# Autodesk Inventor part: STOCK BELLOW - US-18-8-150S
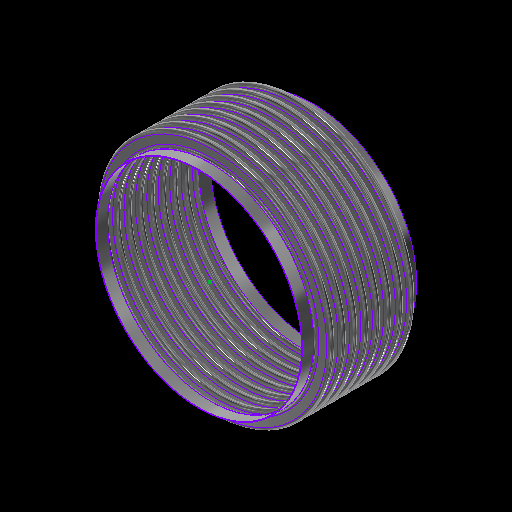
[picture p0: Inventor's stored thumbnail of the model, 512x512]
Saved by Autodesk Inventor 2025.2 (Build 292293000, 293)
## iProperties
Category: 16 GA (0.060 THICK)
RuleStatus: InUse
Created: 2024-01
Part Number: STOCK BELLOW - US-18-8-150S
Project: =STOCK BELLOWS: <Stock Number><SFILL>
Material: ASTM A240-304
Description: =STOCK BELLOWS: <Stock Number>, <SID_> I.D., <SOD_> O.D., <SPLY_> PLY, <Category>, <SNET_CONS> CONS.<PITCH_><STANGENT_> TANGENT<SFILL>
Document SubType Name: Sheet Metal
Designer: GS
Stock Number: U.S-18-8-150S
Surface Area: 20016.7 cm^2
Volume: 1515.23 cm^3
Sheet Metal Rule: Default
Appearance: STAINLESS STEEL
Mass: 12208.7 g
Density: 8.05729 g/cm^3
THK: 0.036
ID: 3.500
OD: 4.250
CONS_: 2
PITCH: 0.500
TANGENT: 0.500
BELLOWS_UPSET: 0.000
d79: 1.000
d82: 1.000
d83: 26.000
d84: 24.000
d174: 8
d214: 8
STHK_: 0.060
SID_: 18.000
SOD_: 20.500
SPITCH_: 1.000
STANGENT__: 1.000
SBELLOWS_UPSET_: 0.000
SDIFF_TAN: 1.000
d252: 2
d275: 2
d287: 0.050
d289: 0.500
d290: 0.000
SOD_NECK: 18 1/8
PLY: 1
PSET: 4.178
PBAR: 1.035
COUNTER: 1.500
NET_TUBE: 3.071
CONS: 2
S_CONS: 0
NET_CONS: 2
ID_M: 88.90 mm
OD_M: 107.95 mm
THK_M: 0.91 mm
ID_U: 3.500 in
OD_U: 4.250 in
THK_U: 0.036 in
TANGENT2: 0.500
TAN_TO_TAN: 1.000 in
d80: 2.571
d81: 10
SID: 2.375
SCONS_: 8
SPITCH: 0.250
STANGENT_: 1.000
SBELLOWS_UPSET: 0.000
SNET_CONS: 8
SS_CONS: 0
SCONS: 8
d190: 8
d191: 1
d192: 1
d193: 8
d194: 0
SIZE: 18.00
PRESSURE: 150
d230: 8
STANGENT: 4.000
SPLY_: 1
d233: 8
d234: 0
d263: 2
d265: 1
d268: 2
d269: 0
d286: 2
d288: 1
d291: 2
d292: 0
SREROLL: 0.750
BLETP: 0.000 ul
PRES_Copy: 85
MATTABLE: 20 GA (0.036 THICK)
PART_NUMBER: U.S-18-8-150S
PITCH_: =, <SPITCH_> PITCH,
CFILL: .
SFILL: .
MESH: ,
COMP: 1.5
EXT: 0.75
LAT: 0.20
ANG: 516
ASR: 5052
LSR: 39491
ANSR: 3676
PRES: 150
COMPM: 15.0
EXTM: 7.5
LATM: 2.00
ASRM: 884.757
PRESM: 10.342
LSRM: 6916.059
ANSRM: 643.778
TEMPMIN: 20
TEMPMAX: 800
TEMPMINM: -7
TEMPMAXM: 427
WEIGHTM: 12.209
WEIGHT: 26.915
Author: GS
Keywords: 20 GA (0.036 THICK)
Comments: =STOCK BELLOW - <STOCK NUMBER>
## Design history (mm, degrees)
sketch "Sketch2"
  geometry: L1 (0, -177.245)-(0, 562.856) reference; L2 (45.364, 0)-(44.45, 0); L3 (48.082, -2.718)-(50.343, -2.718); L4 (48.082, -3.632)-(50.343, -3.632); L5 (50.343, -9.982)-(48.082, -9.982); L6 (50.343, -9.068)-(48.082, -9.068); L7 (45.364, -12.7)-(44.45, -12.7); L8 (48.082, 0)-(48.082, -12.7); L9 (50.343, -6.35)-(53.975, -6.35); L10 (44.45, 0)-(44.45, -12.7); L11 (20.376, 102.841)-(20.376, 101.926); L12 (58.262, 457.127)-(58.262, 349.177); L13 (58.262, 444.427)-(58.262, 336.477); L14 (93.133, -58.817)-(93.133, -71.517); L15 (118.746, -66.401)-(118.746, -66.401); L16 (50.343, -9.068)-(50.343, -9.982); L17 (48.082, -9.068)-(48.082, -9.982); L18 (48.082, -9.525)-(50.343, -9.525); L19 (53.975, 0)-(53.975, -12.7); L20 (-50.343, -9.068)-(-50.343, -9.982); L21 (-50.343, -2.718)-(-48.082, -2.718); L22 (-50.343, -3.632)-(-48.082, -3.632); L23 (-48.082, -9.068)-(-50.343, -9.068); L24 (-50.343, -9.525)-(-48.082, -9.525); L25 (-48.082, -9.982)-(-50.343, -9.982); L26 (-48.082, -9.068)-(-48.082, -9.982); L27 (-44.45, 0.653)-(-44.45, -12.047); L28 (-48.082, -6.35)-(-44.45, -6.35); L29 (-50.343, 0.653)-(-50.343, -12.7); L30 (-53.061, 0)-(-53.975, 0); L31 (-53.975, 0)-(-53.975, -12.7); L32 (-53.061, -12.7)-(-53.975, -12.7); A1 r 2.718 centre (48.082, 0) between (45.364, 0) and (48.082, -2.718); A2 r 3.632 centre (48.082, 0) between (44.45, 0) and (48.082, -3.632); A3 r 3.632 centre (50.343, -6.35) between (50.343, -9.982) and (50.343, -2.718); A4 r 2.718 centre (50.343, -6.35) between (50.343, -9.068) and (50.343, -3.632); A5 r 2.718 centre (48.082, -12.7) between (48.082, -9.982) and (45.364, -12.7); A6 r 3.632 centre (48.082, -12.7) between (48.082, -9.068) and (44.45, -12.7); A7 r 3.175 centre (50.343, -6.35) between (50.343, -9.525) and (53.518, -6.35); A8 r 3.175 centre (48.082, -12.7) between (48.082, -9.525) and (44.907, -12.7); A9 r 2.718 centre (-50.343, -12.7) between (-50.343, -9.982) and (-53.061, -12.7); A10 r 2.718 centre (-48.082, -6.35) between (-48.082, -9.068) and (-48.082, -3.632); A11 r 3.175 centre (-48.082, -6.35) between (-48.082, -9.525) and (-44.907, -6.35); A12 r 3.632 centre (-48.082, -6.35) between (-48.082, -9.982) and (-48.082, -2.718); A13 r 3.175 centre (-50.343, -12.7) between (-50.343, -9.525) and (-53.518, -12.7); A14 r 3.632 centre (-50.343, -12.7) between (-50.343, -9.068) and (-53.975, -12.7); A15 r 2.718 centre (-50.343, 0) between (-53.061, 0) and (-50.343, -2.718); A16 r 3.632 centre (-50.343, 0) between (-53.975, 0) and (-50.343, -3.632); 10 further points
  constraints: 62 end point, 38 point on circle, 20 tangent, 16 centre point, 12 parallel, 9 midpoint, 7 vertical, 6 coincident, 6 concentric, 6 point on line, 4 equal radius, 4 perpendicular, 3 horizontal, 1 collinear, 1 horizontal alignment, 10 other
  dimensions: "THK" = 0.9144 distance of L11.start L11.end; "ID" = 88.9 distance of L11.end point (20.376, 13.026); "OD" = 107.95 distance of L12.start L12.end; "PITCH" = 12.7 distance of L12.start L13.start; "TANGENT" = 12.7 distance of L14.start L14.end; "BELLOWS_UPSET" = 0 distance of L15.start L15.end; "d43" = 88.9 diameter of L10 L1 (= ID); "d44" = 107.95 diameter of L9.end L1 (= OD); "d45" = 0.9144 distance between parallel lines of L5 L6 (computed from THK, PLY); "d46" = 3.6322 radius of A3 (computed from PITCH, THK, PLY); "UPSET_PITCH" = 12.7 distance of L2.end L7.end (derived); "SIDEWALL_ANGLE" = 360 deg dimension on L3 L9 (derived); "CON_GAP" = 5.4356 distance of point (48.082, -9.068) point (48.082, -3.632) (derived); "TAN1" = 4.98728 dimension on A8 (derived); "TAN2" = 4.98728 dimension on A7 (derived); "LEG1" = 2.2606 distance of L18.start L18.end (derived); "d278" = 0.9144 distance between parallel lines of L25 L23 (derived); "d279" = 3.6322 radius of A12 (derived); "d280" = 12.7 distance of L30.end L31.end (derived); "d281" = 360 deg dimension on L21 L28 (derived); "d282" = 5.4356 distance of point (-50.343, -9.068) point (-50.343, -3.632) (derived); "d283" = 4.98728 dimension on A13 (derived); "d284" = 4.98728 dimension on A11 (derived); "d285" = 2.2606 distance of L24.start L24.end (derived); "d293" = 88.9 diameter of L27 L1 (derived); "d294" = 107.95 diameter of L31 L1 (derived)
  node "Sketch Rectangular Pattern1" dims "d31" = 25.4, "ID" = 88.9
  node "Sketch Rectangular Pattern2" dims "d39" = 25.4, "PITCH" = 12.7
revolve "CONS" stored, may be unused: angle "d48" = 90 deg
node "BELLOW MIDPLANE"
pattern_linear "Rectangular Pattern2" dims "d52" = 12.7 (= UPSET_PITCH)
sketch "Sketch5"
  geometry: C1 r 45.364 at (0, 0) reference; C2 r 44.45 at (0, 0) reference
extrude "TANGENT" new body sketch "Sketch5" distance "d53" = 12.7 (= TANGENT); taper "d54" = 0 deg
revolve "SAMETAN" stored, may be unused: angle "d65" = 90 deg
revolve "DIFFTAN" stored, may be unused: angle "d70" = 90 deg
sketch "Sketch9"
  geometry: L1 (53.319, 0)-(-53.319, 0) reference; L2 (0, -17.78)-(0, 17.78) reference; L3 (38.085, 0)-(-38.085, 0); L4 (38.085, -11.906)-(38.085, 11.906); L5 (25.385, -11.906)-(25.385, 11.906); L6 (13.15, 11.906)-(13.15, -11.906); L7 (-25.385, -11.906)-(-25.385, 11.906); L8 (-38.085, -11.906)-(-38.085, 11.906); L9 (37.291, -11.906)-(37.291, 11.906); L10 (38.085, -11.906)-(37.291, -11.906); L11 (38.085, 11.906)-(37.291, 11.906); L12 (13.546, 11.906)-(12.753, 11.906); L13 (12.753, 11.906)-(12.753, -11.906); L14 (12.753, -11.906)-(13.546, -11.906); L15 (13.546, -11.906)-(13.546, 11.906); L16 (-13.546, 11.906)-(-13.546, -11.906); L17 (-13.15, 11.906)-(-13.15, -11.906); L18 (-13.546, -11.906)-(-12.753, -11.906); L19 (-12.753, -11.906)-(-12.753, 11.906); L20 (-12.753, 11.906)-(-13.546, 11.906); L21 (-38.085, -11.906)-(-37.291, -11.906); L22 (-37.291, -11.906)-(-37.291, 11.906); L23 (-37.291, 11.906)-(-38.085, 11.906); L24 (-38.085, 11.906)-(-38.085, -11.906); L25 (38.085, -0.397)-(-38.085, -0.397); L26 (-38.085, -0.397)-(-38.085, 0.397); L27 (-38.085, 0.397)-(38.085, 0.397); L28 (38.085, 0.397)-(38.085, -0.397); L29 (-38.085, 11.906)-(38.085, 11.906); L30 (38.085, 11.906)-(38.085, 12.7); L31 (38.085, 12.7)-(-38.085, 12.7); L32 (-38.085, 12.7)-(-38.085, 11.906); L33 (38.085, -11.906)-(-38.085, -11.906); L34 (-38.085, -11.906)-(-38.085, -12.7); L35 (-38.085, -12.7)-(38.085, -12.7); L36 (38.085, -12.7)-(38.085, -11.906); 30 further points
  constraints: 68 end point, 13 midpoint, 13 parallel, 8 horizontal, 7 perpendicular, 6 equal length, 3 point on line, 2 vertical, 14 other
  dimensions: "d115" = 23.8125 distance of L4.start L4.end (derived); "d116" = 12.7 distance between parallel lines of L4 L5 (derived); "d117" = 12.23516 distance between parallel lines of L5 L6 (derived); "d125" = 38.53427 distance between parallel lines of L7 L6 (derived); "d127" = 12.7 distance between parallel lines of L8 L7 (derived); "d128" = 24.93516 distance between parallel lines of L6 L4 (derived); "d130" = 76.16943 distance between parallel lines of L8 L4 (derived); "RULER_THK" = 0.79375 distance between parallel lines of L4 L9; "d135" = 0.79375 distance of L13.end L14.end (derived); "d138" = 26.29911 distance of L13.end L16.end (derived); "d143" = 0.79375 distance of L22.end L8.end (derived); "d144" = 0.79375 distance between parallel lines of L27 L25 (derived)
extrude "RULER" join sketch "Sketch9" distance "d149" = 0.79375 (derived); taper "d150" = 0 deg
extrude "BARS" join sketch "Sketch9" distance "d151" = 0.79375 (derived); taper "d152" = 0 deg
pattern_linear "Rectangular Pattern4" dims "d155" = 26.29911 (derived)
sketch "Sketch13"
  geometry: L1 (93.149, -52.467)-(93.149, -77.867); L2 (230.124, 0)-(228.6, 0); L3 (230.124, -25.4)-(228.6, -25.4); L4 (253.238, -19.812)-(235.712, -19.812); L5 (253.238, -18.288)-(235.712, -18.288); L6 (253.238, -12.7)-(260.35, -12.7); L7 (235.712, -5.588)-(253.238, -5.588); L8 (235.712, 0)-(235.712, -25.4); L9 (228.6, 0)-(228.6, -25.4); L10 (58.254, 24.269)-(58.254, -496.431); L11 (58.254, -1.131)-(58.254, -521.831); L12 (58.254, -51.931)-(58.254, -572.631); L13 (58.254, -77.331)-(58.254, -598.031); L14 (58.254, -102.731)-(58.254, -623.431); L15 (58.254, -128.131)-(58.254, -648.831); L16 (58.254, -153.531)-(58.254, -674.231); L17 (58.254, -26.531)-(58.254, -547.231); L18 (20.376, 103.45)-(20.376, 101.926); L19 (235.712, -7.112)-(253.238, -7.112); L20 (0, -829.767)-(0, 258.986) reference; L21 (-52.07, 0)-(312.42, 0) reference; A1 r 5.588 centre (235.712, 0) between (230.124, 0) and (235.712, -5.588); A2 r 5.588 centre (235.712, -25.4) between (235.712, -19.812) and (230.124, -25.4); A3 r 7.112 centre (235.712, -25.4) between (235.712, -18.288) and (228.6, -25.4); A4 r 5.588 centre (253.238, -12.7) between (253.238, -18.288) and (253.238, -7.112); A5 r 7.112 centre (253.238, -12.7) between (253.238, -19.812) and (253.238, -5.588); A6 r 7.112 centre (235.712, 0) between (228.6, 0) and (235.712, -7.112); 6 further points; 1 other entity
  constraints: 38 end point, 15 point on circle, 9 tangent, 6 centre point, 6 parallel, 5 vertical alignment, 4 point on line, 4 vertical, 3 coincident, 3 concentric, 2 collinear, 2 equal radius, 1 horizontal, 1 perpendicular, 23 other
  dimensions: "SBELLOWS_UPSET_" = 0 distance of point (118.762, -66.401) point (118.762, -66.401); "STOTAL_THK_BELLOW__" = 1.524 distance between parallel lines of L4 L5 (derived); "d224" = 7.112 radius of A5 (derived); "d225" = 25.4 distance of L2.end L3.end (derived); "SSIDEWALL_ANGLE_" = 360 deg dimension on L7 L6 (derived); "SSCON_GAP_" = 11.176 distance of point (235.712, -18.288) point (235.712, -7.112) (derived); "d235" = 457.2 diameter of L9 L20 (derived); "d236" = 520.7 diameter of L6.end L20 (derived)
  node "Sketch Rectangular Pattern4" dims "d228" = 25.4
  node "Sketch Rectangular Pattern5" dims "d229" = 25.4
revolve "SBELLOW" stored, may be unused: angle "d197" = 90 deg
pattern_linear "Rectangular Pattern5" dims "d204" = 25.4 (derived)
revolve "STANGENT" stored, may be unused: angle "d240" = 90 deg
revolve "SSAMETAN" stored, may be unused: angle "d241" = 90 deg
revolve "SDIFFTAN" stored, may be unused: angle "d246" = 90 deg
revolve "INVCON" stored, may be unused: angle "d295" = 90 deg
pattern_linear "Rectangular Pattern6" dims "d298" = 12.7 (derived)
revolve "INVTANGENT" stored, may be unused: angle "d302" = 90 deg
revolve "INVSAMETAN" stored, may be unused: angle "d307" = 90 deg
revolve "INVDIFFTAN" stored, may be unused: angle "d312" = 90 deg
sketch "ID BELLOW MOUNT CALC"
  geometry: L1 (44.45, 0)-(38.1, 0); L2 (38.1, 0)-(38.1, 12.7); L3 (38.1, 12.7)-(44.45, 12.7); L4 (44.45, 12.7)-(44.45, 0); L5 (36.513, 12.7)-(35.598, 12.7); L6 (35.598, 12.7)-(35.598, 0); L7 (35.598, 0)-(36.513, 0); L8 (36.513, 0)-(36.513, 12.7); L9 (0, -2.54)-(0, 15.24) reference; L10 (-8.89, 0)-(53.34, 0) reference; 1 further point
  constraints: 16 end point, 5 parallel, 2 collinear, 2 horizontal, 2 perpendicular
  dimensions: "d314" = 12.7 distance of L5.end L6.end (derived); "d315" = 0.9144 distance of L5.start L5.end (derived); "IG" = 1.5875 distance between parallel lines of L2 L8; "PIPE_OD" = 88.9 diameter of L4 L9; "PIPE_WALL" = 6.35 distance of L2.end L3.end; "ID_MT_BELLOW" = 71.1962 diameter of L6 L9 (derived)
revolve "CFILL" stored, may be unused: angle "d320" = 90 deg
pattern_linear "Rectangular Pattern7" dims "d323" = 12.7 (derived)
revolve "SFILL" stored, may be unused: angle "d324" = 90 deg
pattern_linear "Rectangular Pattern8" dims "d327" = 25.4 (derived)
node "STOCK BELLOW MIDPLANE"
node "BELLOW"
sketch "Sketch6"
  geometry: L1 (-12.7, 45.364)-(0, 45.364); L2 (0, 45.364)-(0, 44.45); L3 (0, 44.45)-(-12.7, 44.45); L4 (-12.7, 44.45)-(-12.7, 45.364); L5 (10.16, 0)-(-60.96, 0) reference; L6 (-38.1, -89.422)-(-38.1, 153.44) reference; 1 further point
  constraints: 8 end point, 2 parallel, 1 horizontal, 1 perpendicular
  dimensions: "d61" = 12.7 distance of L2.end L3.end (derived); "d62" = 0.9144 distance of L1.end L2.end (derived); "d63" = 88.9 diameter of L3 L5 (derived); "d64" = 25.4 distance between parallel lines of L4 L6 (derived)
sketch "Sketch12"
  geometry: 1 further point
sketch "Sketch14"
  geometry: L1 (-25.4, 230.124)-(0, 230.124); L2 (0, 230.124)-(0, 228.6); L3 (0, 228.6)-(-25.4, 228.6); L4 (-25.4, 228.6)-(-25.4, 230.124); L5 (5.08, 0)-(-30.48, 0) reference; L6 (0, -46.025)-(0, 276.149) reference; 1 further point
  constraints: 8 end point, 2 parallel, 1 collinear, 1 horizontal, 1 perpendicular
  dimensions: "d237" = 1.524 distance of L3.end L1.start (derived); "d238" = 457.2 diameter of L3 L5 (derived); "d239" = 25.4 distance of L1.start L1.end (derived); "SOD_NECK" = 460.248 diameter of L1 L5 (derived)
sketch "Sketch15"
  geometry: L1 (-46.025, 0)-(276.149, 0) reference; L2 (228.6, -203.2)-(230.124, -203.2); L3 (230.124, -203.2)-(230.124, -228.6); L4 (230.124, -228.6)-(228.6, -228.6); L5 (228.6, -228.6)-(228.6, -203.2); L6 (0, -276.86)-(0, 60.96) reference; 1 further point
  constraints: 8 end point, 2 parallel, 1 horizontal, 1 perpendicular
  dimensions: "d205" = 25.4 distance of L4.end L2.start (derived); "d206" = 1.524 distance of L3.end L4.end (derived); "d207" = 457.2 diameter of L5 L6 (derived); "d208" = 203.2 distance between parallel lines of L1 L2 (derived)
node "TANGENT_"
node "SAME_TAN"
sketch "Sketch8"
  geometry: L1 (45.364, -25.4)-(44.45, -25.4); L2 (44.45, -25.4)-(44.45, -38.1); L3 (44.45, -38.1)-(45.364, -38.1); L4 (45.364, -38.1)-(45.364, -25.4); L5 (0, -48.26)-(0, 22.86) reference; L6 (-89.422, 0)-(153.44, 0) reference; 1 further point
  constraints: 8 end point, 2 parallel, 1 horizontal, 1 perpendicular
  dimensions: "d66" = 88.9 diameter of L2 L5 (derived); "TOTAL_THK_BELLOW" = 0.9144 distance of L2.end L3.end (derived); "d68" = 25.4 distance between parallel lines of L1 L6 (derived); "d69" = 12.7 distance of L1.end L2.end (derived)
node "DIFF_TAN"
node "Sketch Rectangular Pattern3" dims "d138" = 26.29911 (derived), "d141" = 25.4
node "SBELLOW_"
node "STANGENT_"
node "SSAME_TAN"
sketch "Sketch16"
  geometry: L1 (230.124, -203.2)-(228.6, -203.2); L2 (228.6, -203.2)-(228.6, -228.6); L3 (228.6, -228.6)-(230.124, -228.6); L4 (230.124, -228.6)-(230.124, -203.2); L5 (0, -276.86)-(0, 60.96) reference; L6 (-46.025, 0)-(276.149, 0) reference; 1 further point
  constraints: 8 end point, 2 parallel, 1 horizontal, 1 perpendicular
  dimensions: "SDIFF_TAN" = 25.4 distance of L3.end L1.start; "d243" = 1.524 distance of L2.end L3.end (derived); "d244" = 203.2 distance between parallel lines of L1 L6 (derived); "d245" = 457.2 diameter of L2 L5 (derived)
node "SDIFF_TAN"
body "Solid15"
sketch "Sketch17"
  geometry: L1 (53.975, 12.7)-(53.061, 12.7); L2 (53.061, 12.7)-(53.061, 0); L3 (53.061, 0)-(53.975, 0); L4 (53.975, 0)-(53.975, 12.7); L5 (0, -2.54)-(0, 15.24) reference; L6 (-10.795, 0)-(64.77, 0) reference; 2 further points
  constraints: 8 end point, 2 parallel, 1 horizontal, 1 midpoint, 1 perpendicular, 1 point on line
  dimensions: "INVTANGENT" = 12.7 distance of L3.end L1.start (derived); "d300" = 0.9144 distance of L1.start L1.end (derived); "d301" = 107.95 diameter of L4 L5 (derived)
body "Solid16"
sketch "Sketch18"
  geometry: L1 (53.975, -25.4)-(53.061, -25.4); L2 (53.061, -25.4)-(53.061, -38.1); L3 (53.061, -38.1)-(53.975, -38.1); L4 (53.975, -38.1)-(53.975, -25.4); L5 (-10.795, 0)-(64.77, 0) reference; L6 (0, -48.26)-(0, 22.86) reference; 1 further point
  constraints: 8 end point, 2 parallel, 1 horizontal, 1 perpendicular
  dimensions: "d303" = 25.4 distance between parallel lines of L1 L5 (derived); "d304" = 12.7 distance of L3.end L1.start (derived); "d305" = 0.9144 distance of L2.end L3.end (derived); "d306" = 107.95 diameter of L4 L6 (derived)
body "Solid17"
sketch "Sketch19"
  geometry: L1 (53.975, -25.4)-(53.061, -25.4); L2 (53.061, -25.4)-(53.061, -38.1); L3 (53.061, -38.1)-(53.975, -38.1); L4 (53.975, -38.1)-(53.975, -25.4); L5 (0, -48.26)-(0, 22.86) reference; L6 (-10.795, 0)-(64.77, 0) reference; 1 further point
  constraints: 8 end point, 2 parallel, 1 horizontal, 1 perpendicular
  dimensions: "d308" = 12.7 distance of L1.end L2.end (derived); "d309" = 107.95 diameter of L4 L5 (derived); "d310" = 0.9144 distance of L2.end L3.end (derived); "d311" = 25.4 distance between parallel lines of L1 L6 (derived)
body "Solid18"
body "Solid19"
body "Solid20"
other parameters: "BMPL" = -101.6, "PSET" = 106.1212 (computed from OD, THK, PLY) [user parameter], "PBAR" = 26.29911 (= 0.570796 x PITCH + OD - ID) [user parameter; used in 1 equation term], "COUNTER" = 15 [user parameter], "NET_TUBE" = 77.99823 (computed from CONS_, PBAR, TANGENT) [user parameter], "S_CONS" = 0 [user parameter; used in 1 equation term], "ID_M" = 88.9 (= ID) [user parameter], "OD_M" = 107.95 (= OD) [user parameter], "THK_M" = 0.9144 (= THK) [user parameter], "ID_U" = 88.9 (= ID) [user parameter], "OD_U" = 107.95 (= OD) [user parameter], "THK_U" = 0.9144 (= THK) [user parameter], "D_UNITS" = 0 [user parameter], "TANGENT2" = 12.7 [user parameter], "TAN_TO_TAN" = 25.4 [user parameter], "OD_NECK" = 90.7288 [user parameter], "d79" = 25.4, "d80" = 65.29823 [user parameter], "d82" = 25.4, "d83" = 660.4, "d84" = 609.6, "sa_0" = 4, "FRAME_THK" = 0.79375 [user parameter], "CON_FLAT" = 12.23516 [user parameter], "SID" = 60.325 [user parameter], "SPITCH" = 6.35 [user parameter], "STANGENT_" = 25.4 [user parameter], "SBELLOWS_UPSET" = 0 [user parameter], "SS_CONS" = 0 [user parameter], "STAN_TO_TAN_" = 203.2 [user parameter], "d100" = 1.524 [user parameter], "d191" = 25.4 [user parameter], "d194" = 0 [user parameter], "STANGENT" = 101.6 [user parameter], "d234" = 0 [user parameter], "SUPSET_PITCH_" = 25.4 [user parameter], "d269" = 0 [user parameter], "d287" = 1.27, "d289" = 12.7, "d290" = 0, "d292" = 0 [user parameter], "Thickness" = 3.048 (derived), "KFactor" = 4.4, "BendRadius" = 3.048 (derived), "BendReliefWidth" = 3.048 (derived), "BendReliefDepth" = 1.524 (derived), "CornerReliefSize" = 12.192 (derived), "SeamGap" = 0.00508, "MinimumRemnant" = 6.096 (derived), "TransitionRadius" = 3.048 (derived), "JacobiRadiusSize" = 3.048 (derived), "GapSize" = 3.048 (derived), "SREROLL" = 19.05 [user parameter], "CUR_STK_PITCH" = 25.4 [user parameter], "d328" = -101.6 (derived), "ASR" = 50520 [user parameter], "LSR" = 394910 [user parameter], "ANSR" = 36760 [user parameter], "BLETP" = 0 [user parameter], "ASRM" = 8847.5676 [user parameter], "PRESM" = 103.41975 [user parameter], "LSRM" = 69160.5883 [user parameter], "ANSRM" = 6437.7788 [user parameter], "TEMPMIN" = 2664.83333 [user parameter], "TEMPMAX" = 6998.16667 [user parameter], "TEMPMINM" = 2664.83333 [user parameter], "TEMPMAXM" = 6998.16667 [user parameter], "WEIGHT" = 122.08656 [user parameter], "WEIGHTM" = 0.12209 [user parameter]
